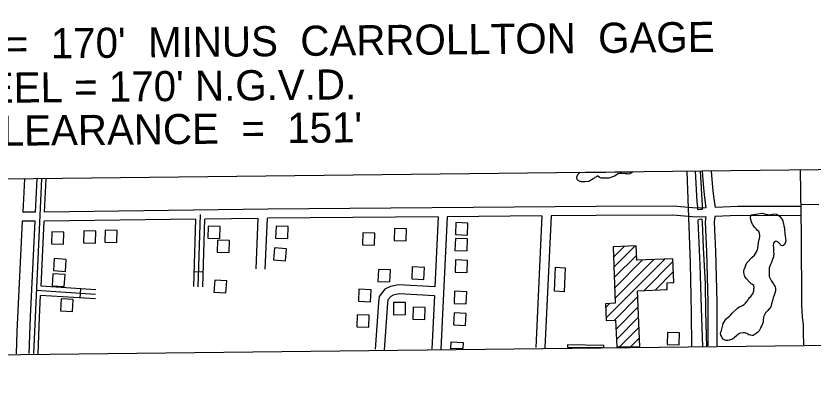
# Model space of a CAD drawing. Extents: x 3677843 to 3715951, y 511991 to 537744.
# Drawn here: x 3689692 to 3692337, y 517405 to 518617 of the extents above; entities that cross this region are included whole.
import ezdxf

# ---------------------------------------------------------------- set-up
doc = ezdxf.new("R2010")
doc.units = 0
for name, color, linetype in [('V-ANNO-SYMB', 7, 'Continuous'), ('V-BLDG-OTLN', 7, 'Continuous'), ('V-GRID-FRAM', 7, 'Continuous'), ('V-ROAD-CNTR', 7, 'Continuous'), ('V-SITE-VEGE', 7, 'Continuous'), ('V-TOPO-SHOR', 7, 'Continuous')]:
    doc.layers.add(name, color=color, linetype=linetype)

msp = doc.modelspace()

# ---------------------------------------------------------------- linework, layer by layer
at = {"layer": 'V-ANNO-SYMB'}
msp.add_lwpolyline([(3687883.4, 520947), (3700228.3, 521088.8), (3700261.6, 518197.4), (3687916.7, 518055.5)], close=True, dxfattribs=at)
at = {"layer": 'V-BLDG-OTLN'}
for p, q in [((3691674.8, 517817), (3691710.2, 517852.5)), ((3691676.1, 517783), (3691747, 517853.9)), ((3691650.1, 517615.5), (3691844.8, 517810.2)), ((3691677.4, 517748.9), (3691751.6, 517823.1)), ((3691678.7, 517714.9), (3691771.2, 517807.4)), ((3691680, 517680.8), (3691808, 517808.8)), ((3691776.1, 517706.2), (3691871.9, 517802)), ((3691812.9, 517707.6), (3691873.2, 517767.9)), ((3691873, 517732.4), (3691874.5, 517733.9)), ((3691849.7, 517709), (3691853.2, 517712.6)), ((3691677.7, 517607.8), (3691755.4, 517685.5)), ((3691648.8, 517649.6), (3691661.9, 517662.7)), ((3691683, 517577.7), (3691756.7, 517651.4)), ((3691684.3, 517543.7), (3691758, 517617.4)), ((3691694.8, 517518.8), (3691759.3, 517583.3)), ((3691730.6, 517519.2), (3691760.6, 517549.3)), ((3691175, 517512.9), (3691134.9, 517512.4)), ((3691522.4, 517516.8), (3691642.9, 517518.2))]:
    msp.add_line(p, q, dxfattribs=at)
for points in [[(3690369.5, 517918.5), (3690329.5, 517919.7), (3690328.3, 517879.7), (3690368.3, 517878.6)], [(3690594.9, 517918.2), (3690554.9, 517919.4), (3690553.7, 517879.4), (3690593.7, 517878.2)], [(3690987.7, 517910.7), (3690947.7, 517911.9), (3690946.5, 517871.9), (3690986.5, 517870.7)], [(3691151.4, 517931.5), (3691149.9, 517891.5), (3691189.9, 517890), (3691191.4, 517929.9)], [(3689850.8, 517899.6), (3689810.8, 517900.8), (3689809.6, 517860.8), (3689849.6, 517859.6)], [(3689956.9, 517902.9), (3689916.9, 517904.1), (3689915.7, 517864.1), (3689955.7, 517862.9)], [(3690027.6, 517905), (3689987.6, 517906.2), (3689986.4, 517866.2), (3690026.4, 517865)], [(3690882.8, 517896.7), (3690842.8, 517897.9), (3690841.6, 517857.9), (3690881.6, 517856.8)], [(3690400.3, 517872.2), (3690360.3, 517873.4), (3690359.2, 517833.4), (3690399.1, 517832.2)], [(3691150.3, 517879), (3691148.7, 517839.1), (3691188.7, 517837.5), (3691190.2, 517877.5)], [(3690549.4, 517847.2), (3690546.7, 517807.3), (3690586.6, 517804.5), (3690589.3, 517844.4)], [(3691673.5, 517851.1), (3691680.7, 517663.5), (3691648.3, 517662.2), (3691650.4, 517606.8), (3691681.8, 517608), (3691685.2, 517518.7), (3691761.8, 517519.6), (3691754.6, 517705.4), (3691853.3, 517709.2), (3691852.5, 517731.6), (3691874.5, 517732.5), (3691871.5, 517811.3), (3691752.2, 517806.7), (3691750.4, 517854)], [(3689818.9, 517812), (3689816.1, 517772.1), (3689856, 517769.4), (3689858.8, 517809.3)], [(3691150.6, 517807.3), (3691149.1, 517767.3), (3691189, 517765.8), (3691190.6, 517805.8)], [(3691005.2, 517744.4), (3691045.2, 517742.5), (3691047.1, 517782.4), (3691007.1, 517784.3)], [(3691513.9, 517781.5), (3691510.5, 517701.9), (3691478.7, 517703.3), (3691482.1, 517782.9)], [(3689814.8, 517761.3), (3689812, 517721.4), (3689851.9, 517718.7), (3689854.7, 517758.6)], [(3690892.5, 517736.1), (3690932.4, 517734.2), (3690934.3, 517774.2), (3690894.4, 517776)], [(3690351.7, 517740.4), (3690348.9, 517700.5), (3690388.8, 517697.7), (3690391.6, 517737.6)], [(3690868.4, 517668.6), (3690870.1, 517708.6), (3690830.1, 517710.3), (3690828.4, 517670.4)], [(3691147.5, 517703.2), (3691146, 517663.2), (3691185.9, 517661.7), (3691187.5, 517701.7)], [(3689842.1, 517678.8), (3689839.4, 517638.9), (3689879.3, 517636.1), (3689882, 517676)], [(3690984.2, 517666.2), (3690944.2, 517665.7), (3690944.6, 517625.7), (3690984.6, 517626.2)], [(3691048.9, 517609.2), (3691050.3, 517649.2), (3691010.3, 517650.5), (3691008.9, 517610.5)], [(3690862.8, 517583.8), (3690864.5, 517623.7), (3690824.5, 517625.5), (3690822.8, 517585.5)], [(3691145.6, 517631.5), (3691144.1, 517591.5), (3691184, 517590), (3691185.6, 517629.9)], [(3691854, 517567), (3691852.4, 517527.1), (3691892.4, 517525.5), (3691893.9, 517565.5)]]:
    msp.add_lwpolyline(points, close=True, dxfattribs=at)
for points in [[(3691134.9, 517512.4), (3691135.8, 517535)], [(3691135.8, 517535), (3691175.8, 517533.5), (3691175, 517512.9)], [(3691522.6, 517526.1), (3691522.4, 517516.8)], [(3691642.9, 517518.2), (3691643, 517523.5), (3691522.6, 517526.1)]]:
    msp.add_lwpolyline(points, dxfattribs=at)
at = {"layer": 'V-GRID-FRAM'}
msp.add_lwpolyline([(3681899.6, 535587.1), (3713561.2, 535950.9), (3713778.1, 517769.3), (3682100.6, 517405.3), (3681899.6, 535587.1)], dxfattribs=at)
at = {"layer": 'V-ROAD-CNTR'}
for p, q in [((3690283.3, 517768.8), (3690313.3, 517768)), ((3689905.5, 517681.3), (3689907.5, 517711.3))]:
    msp.add_line(p, q, dxfattribs=at)
for points in [[(3691917.9, 518101.5), (3691929.1, 517796.6), (3691932, 517630.6), (3691933.1, 517521.6)], [(3691969.1, 518102.1), (3691973, 518045.2), (3691976.8, 518014.3), (3691981.6, 517980.9)], [(3691999.1, 518102.4), (3692002.9, 518048.1), (3692006.6, 518018.2), (3692011.7, 517982)], [(3692294.2, 518105.8), (3692297, 517890.2), (3692298.5, 517657), (3692301, 517617.7), (3692303.5, 517592.9), (3692303.5, 517561.8), (3692304.8, 517529.4), (3692305.4, 517525.8)], [(3689720, 518076.2), (3689714.5, 517966.2)], [(3689777, 518076.9), (3689755.4, 517617.9), (3689750.7, 517496.5)], [(3689756.8, 517966.1), (3689762, 518076.7)], [(3689786.8, 517966.3), (3689792, 518077.1)], [(3692295.7, 517992.3), (3692356.3, 517991.8)], [(3689756.8, 517966.1), (3689714.5, 517966.2)], [(3691981.6, 517980.9), (3691949.8, 517979.8), (3691873.1, 517986.4), (3691616.9, 517984.9), (3690527.5, 517975.8), (3689786.8, 517966.3)], [(3692296, 517984.3), (3692087, 517984.6), (3692011.7, 517982)], [(3689713, 517936.2), (3689694.8, 517569.8), (3689692.7, 517495.2)], [(3689755.3, 517936.1), (3689713, 517936.2)], [(3689735.7, 517497.1), (3689740.4, 517618.5), (3689755.3, 517936.1)], [(3689775.2, 517719.9), (3689785.4, 517936.3)], [(3690288.3, 517942.7), (3689785.4, 517936.3)], [(3690281.9, 517718.8), (3690288.3, 517942.7)], [(3690296.9, 517718.4), (3690303.8, 517957.9)], [(3690311.9, 517718), (3690318.3, 517943.1)], [(3690496.1, 517945.4), (3690318.3, 517943.1)], [(3690489.1, 517778.1), (3690496.1, 517945.4)], [(3690519.1, 517776.9), (3690526.1, 517945.8)], [(3691092.4, 517950.5), (3690526.1, 517945.8)], [(3691092.4, 517950.5), (3691081.7, 517718.1)], [(3691122.4, 517950.7), (3691102.3, 517511.2)], [(3691437.4, 517953.4), (3691122.4, 517950.7)], [(3691437.4, 517953.4), (3691417.4, 517516.5)], [(3691467.4, 517953.6), (3691447.3, 517515.1)], [(3691980.7, 517950.9), (3691949.1, 517949.8), (3691871.9, 517956.4), (3691617.2, 517954.9), (3691467.4, 517953.6)], [(3691980.7, 517950.9), (3691979, 517934.1), (3691982.8, 517834.5), (3691987.7, 517667.3), (3691987.7, 517522.4)], [(3692010.9, 517951.9), (3692009, 517933.2), (3692012.8, 517835.5), (3692017.7, 517667.8), (3692017.7, 517522.4)], [(3692296, 517954.3), (3692087.5, 517954.6), (3692010.9, 517951.9)], [(3691081.7, 517718.1), (3690961.4, 517724.6), (3690934.3, 517719.3), (3690915.9, 517710), (3690896.6, 517686), (3690895.3, 517667), (3690891.4, 517619), (3690884.1, 517510.7)], [(3689956.4, 517693.1), (3689759.5, 517705.8)], [(3689957.3, 517708), (3689775.2, 517719.9)], [(3689765.7, 517495.9), (3689770.4, 517617.3), (3689773.8, 517689.9)], [(3689955.4, 517678.1), (3689773.8, 517689.9)], [(3691080.4, 517688.1), (3690963.5, 517694.4), (3690944.1, 517690.7), (3690935.3, 517686.2), (3690925.9, 517674.5), (3690925.3, 517664.8), (3690921.4, 517616.8), (3690914, 517508.7)], [(3691080.4, 517688.1), (3691072.4, 517512.5)]]:
    msp.add_lwpolyline(points, dxfattribs=at)
at = {"layer": 'V-SITE-VEGE'}
for p, q in [((3691556.7, 518091.1), (3691561.5, 518096.6)), ((3691561.5, 518096.6), (3691562.3, 518097.4)), ((3691562.3, 518097.4), (3691737.9, 518099.4)), ((3691694.6, 518094.4), (3691690.3, 518092.8)), ((3691701.7, 518094.5), (3691694.6, 518094.4)), ((3691713.2, 518093), (3691701.7, 518094.5)), ((3691736.6, 518098.1), (3691727.4, 518093.1)), ((3691737.9, 518099.4), (3691736.6, 518098.1)), ((3691552.9, 518081.8), (3691556.7, 518091.1)), ((3691554.6, 518074.7), (3691552.9, 518081.8)), ((3691557.4, 518071.5), (3691554.6, 518074.7)), ((3691561.8, 518068.8), (3691557.4, 518071.5)), ((3691568.3, 518066.7), (3691561.8, 518068.8)), ((3691592.3, 518068), (3691580.3, 518066.2)), ((3691598.8, 518070.7), (3691592.3, 518068)), ((3691601.5, 518073), (3691598.8, 518070.7)), ((3691607, 518076.8), (3691601.5, 518073)), ((3691609.7, 518077.9), (3691607, 518076.8)), ((3691612.9, 518080.7), (3691609.7, 518077.9)), ((3691617.8, 518083.5), (3691612.9, 518080.7)), ((3691621.1, 518086.2), (3691617.8, 518083.5)), ((3691627.7, 518081.3), (3691621.1, 518086.2)), ((3691634.8, 518079.2), (3691627.7, 518081.3)), ((3691644, 518078.8), (3691634.8, 518079.2)), ((3691653.9, 518078.8), (3691644, 518078.8)), ((3691658.8, 518079.4), (3691653.9, 518078.8)), ((3691671.3, 518082.8), (3691658.8, 518079.4)), ((3691677.8, 518085.6), (3691671.3, 518082.8)), ((3691690.3, 518092.8), (3691677.8, 518085.6)), ((3691720.8, 518093), (3691713.2, 518093)), ((3691723, 518092.5), (3691720.8, 518093)), ((3691727.4, 518093.1), (3691723, 518092.5)), ((3691574.9, 518066.2), (3691568.3, 518066.7)), ((3691580.3, 518066.2), (3691574.9, 518066.2))]:
    msp.add_line(p, q, dxfattribs=at)
for points in [[(3692131.6, 517956.8), (3692168.6, 517963.1), (3692171.4, 517961.5), (3692183.9, 517958.3), (3692187.2, 517957.8), (3692192.7, 517957.3), (3692206.8, 517960.1), (3692215.6, 517959.7), (3692220.5, 517957), (3692225.4, 517953.2), (3692233.7, 517943.4), (3692234.8, 517940.2), (3692236.5, 517936.9), (3692238.2, 517930.9), (3692238.7, 517927.1), (3692240.4, 517920.6), (3692241.6, 517913), (3692241.6, 517907.5), (3692242.2, 517904.2), (3692242.8, 517899.9), (3692243.4, 517893.3), (3692244.5, 517886.3), (3692245.1, 517879.2), (3692246.3, 517871), (3692244.7, 517863.3), (3692242.6, 517860.1), (3692240.9, 517857.3), (3692236.6, 517854), (3692230.6, 517855.6), (3692228.9, 517857.8), (3692227.3, 517859.4), (3692220.7, 517866.4), (3692216.9, 517868.6), (3692213.6, 517869.6), (3692210.3, 517868.5), (3692205.4, 517863.6), (3692204.4, 517858.7), (3692205.1, 517845), (3692205.6, 517839), (3692205.7, 517836.8), (3692206.3, 517825.4), (3692205.8, 517822.1), (3692205.3, 517817.2), (3692201.5, 517806.8), (3692200, 517801.9), (3692197.8, 517796.4), (3692195.1, 517792), (3692191.4, 517781.1), (3692191.4, 517776.2), (3692190.9, 517769.1), (3692191.1, 517752.7), (3692196.6, 517741.9), (3692199.4, 517737), (3692204.4, 517728.8), (3692206, 517726.7), (3692211, 517718), (3692212.1, 517713.6), (3692212.7, 517707.1), (3692212.2, 517704.4), (3692209.5, 517696.7), (3692206.9, 517687.4), (3692204.2, 517682.5), (3692203.2, 517675.9), (3692202.1, 517673.2), (3692199.5, 517661.7), (3692196.8, 517651.9), (3692186.6, 517639.2), (3692179.5, 517632.1), (3692173.1, 517620.6), (3692172, 517616.8), (3692171, 517608), (3692171.1, 517600.4), (3692169.5, 517594.9)], [(3692169.5, 517594.9), (3692167.3, 517590), (3692163.6, 517584), (3692162, 517580.7), (3692157.7, 517572.5), (3692152.8, 517567), (3692148.5, 517563.1), (3692138.2, 517557), (3692134.9, 517557), (3692130.5, 517557.5), (3692127.8, 517558), (3692124, 517559.1), (3692120.7, 517561.2), (3692117.4, 517562.8), (3692112.5, 517564.4), (3692109.2, 517565), (3692104.8, 517565.5), (3692097.2, 517564.3), (3692092.8, 517563.2), (3692089.6, 517561.5), (3692070.1, 517543.9), (3692065.7, 517542.8), (3692054.3, 517540.5), (3692047.7, 517540.5), (3692045, 517541.5), (3692038.4, 517544.7), (3692035.7, 517549.1), (3692032.9, 517554.5), (3692031.2, 517557.2), (3692030.1, 517564.9), (3692031.2, 517568.1), (3692031.7, 517570.3), (3692032.8, 517573.1), (3692035.9, 517586.2), (3692037, 517591.1), (3692039.1, 517596.6), (3692048.3, 517611.4), (3692049.9, 517613), (3692055.3, 517616.9), (3692059.6, 517620.2), (3692063.4, 517624.6), (3692068.3, 517631.2), (3692070.4, 517632.8), (3692082.3, 517644.4), (3692087.2, 517648.2), (3692092.6, 517652.1), (3692102.4, 517656.5), (3692108.4, 517659.9), (3692112.2, 517663.7), (3692118.1, 517670.3), (3692121.4, 517675.2), (3692123.5, 517679.6), (3692125.7, 517682.4), (3692130, 517686.2), (3692134.9, 517692.3), (3692136.5, 517694.5), (3692139.7, 517701), (3692140.2, 517705.4), (3692140.7, 517711.9), (3692141.2, 517714.7), (3692140.6, 517722.3), (3692135.7, 517726.1), (3692131.8, 517728.2), (3692128.5, 517730.9), (3692114.8, 517745.5), (3692110.4, 517752.1), (3692109.2, 517755.9), (3692108.1, 517760.2), (3692107, 517767.3), (3692107.5, 517773.3), (3692109.1, 517778.2), (3692114.4, 517791.9), (3692117.6, 517797.4), (3692120.3, 517800.7), (3692131.1, 517813.3), (3692133.3, 517815.5), (3692142, 517823.2), (3692145.7, 517828.7), (3692149.5, 517834.7), (3692152.7, 517841.9), (3692153.2, 517846.2), (3692154.8, 517854.4), (3692155.8, 517865.3), (3692158.4, 517875.2), (3692159, 517879), (3692160.5, 517885.6), (3692160.5, 517891), (3692159.4, 517894.8), (3692156.6, 517901.3), (3692151.1, 517906.8), (3692147.8, 517910.5), (3692142.8, 517916), (3692140.1, 517919.2), (3692138.4, 517922.5), (3692136.2, 517924.6), (3692132.3, 517933.9), (3692130.1, 517941.5), (3692129, 517944.8), (3692129.5, 517948), (3692130, 517953.5), (3692131.6, 517956.8)]]:
    msp.add_lwpolyline(points, dxfattribs=at)
at = {"layer": 'V-TOPO-SHOR'}
for points in [[(3691952.5, 518000.2), (3691947.7, 518082.6), (3691946.5, 518101.8)], [(3691961.8, 518102), (3691968.9, 517987.7), (3691969.6, 517978.9), (3691969.2, 517976.5), (3691968.6, 517975.1), (3691962.7, 517974.4), (3691956.8, 517973.5), (3691954.5, 517975), (3691954.2, 517982.1), (3691953.1, 517992.5), (3691952.5, 518000.2)], [(3691962.4, 517791.4), (3691958.3, 517889.1), (3691955.9, 517937.2), (3691956.5, 517941.5), (3691964.4, 517943.8), (3691967.9, 517943), (3691968.8, 517931.6), (3691972.6, 517848.5), (3691978.4, 517728.6), (3691980.5, 517636.8), (3691983.6, 517518.9)], [(3691970.7, 517518.7), (3691966.7, 517646.9), (3691962.4, 517791.4)]]:
    msp.add_lwpolyline(points, dxfattribs=at)

# ---------------------------------------------------------------- texts
at = {"layer": 'V-ANNO-SYMB'}
for s, p in [("VERTICAL  CLEARANCE  =  170'  MINUS  CARROLLTON  GAGE", (3688035.6, 518459)), ("LOWEST STEEL = 170' N.G.V.D.", (3688822.9, 518321)), ("VERTICAL  CLEARANCE  =  151'", (3688820.2, 518178))]:
    msp.add_text(s, height=100, rotation=0.5666, dxfattribs=at).set_placement(p)

doc.saveas('drawing.dxf')
